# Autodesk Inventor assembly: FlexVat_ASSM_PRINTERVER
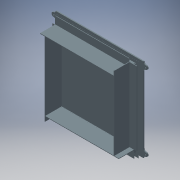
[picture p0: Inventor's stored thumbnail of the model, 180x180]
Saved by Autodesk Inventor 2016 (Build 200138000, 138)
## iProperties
Created: 2015-11
Part Number: FlexVat_ASSM_PRINTERVER
Document SubType Name: Assembly
Designer: John
Author: John
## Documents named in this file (8)
- D:\3D Printer Designs\John Ledden Designs\DLP Printer\V0-4\FlexVat_ASSM_PRINTERVER.iam
- D:\3D Printer Designs\John Ledden Designs\DLP Printer\V0-4\FlexVat_Base.ipt
- D:\3D Printer Designs\John Ledden Designs\DLP Printer\V0-4\Clear_VatBottom.ipt
- D:\3D Printer Designs\John Ledden Designs\DLP Printer\V0-4\FEP_Film.ipt
- D:\3D Printer Designs\John Ledden Designs\DLP Printer\V0-4\Clamp_Bottom.ipt
- D:\3D Printer Designs\John Ledden Designs\DLP Printer\V0-4\Gasket_Strip.ipt
- D:\3D Printer Designs\John Ledden Designs\DLP Printer\V0-4\Clamp_Top.ipt
- D:\3D Printer Designs\John Ledden Designs\DLP Printer\V0-4\VatWall.ipt
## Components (13 placed, 13 different names)
1. FlexVat_Base_1070
2. Clear_VatBottom_1071
3. FEP_Film_1072
4. Clamp_Bottom_1073
5. Gasket_Strip_1074
6. Gasket_Strip_1075
7. Gasket_Strip_1076
8. Gasket_Strip_1077
9. Clamp_Top_1078
10. VatWall_1079
11. VatWall_1080
12. VatWall_1081
13. VatWall_1082
